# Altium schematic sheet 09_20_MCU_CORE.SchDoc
size 289 x 404 mm
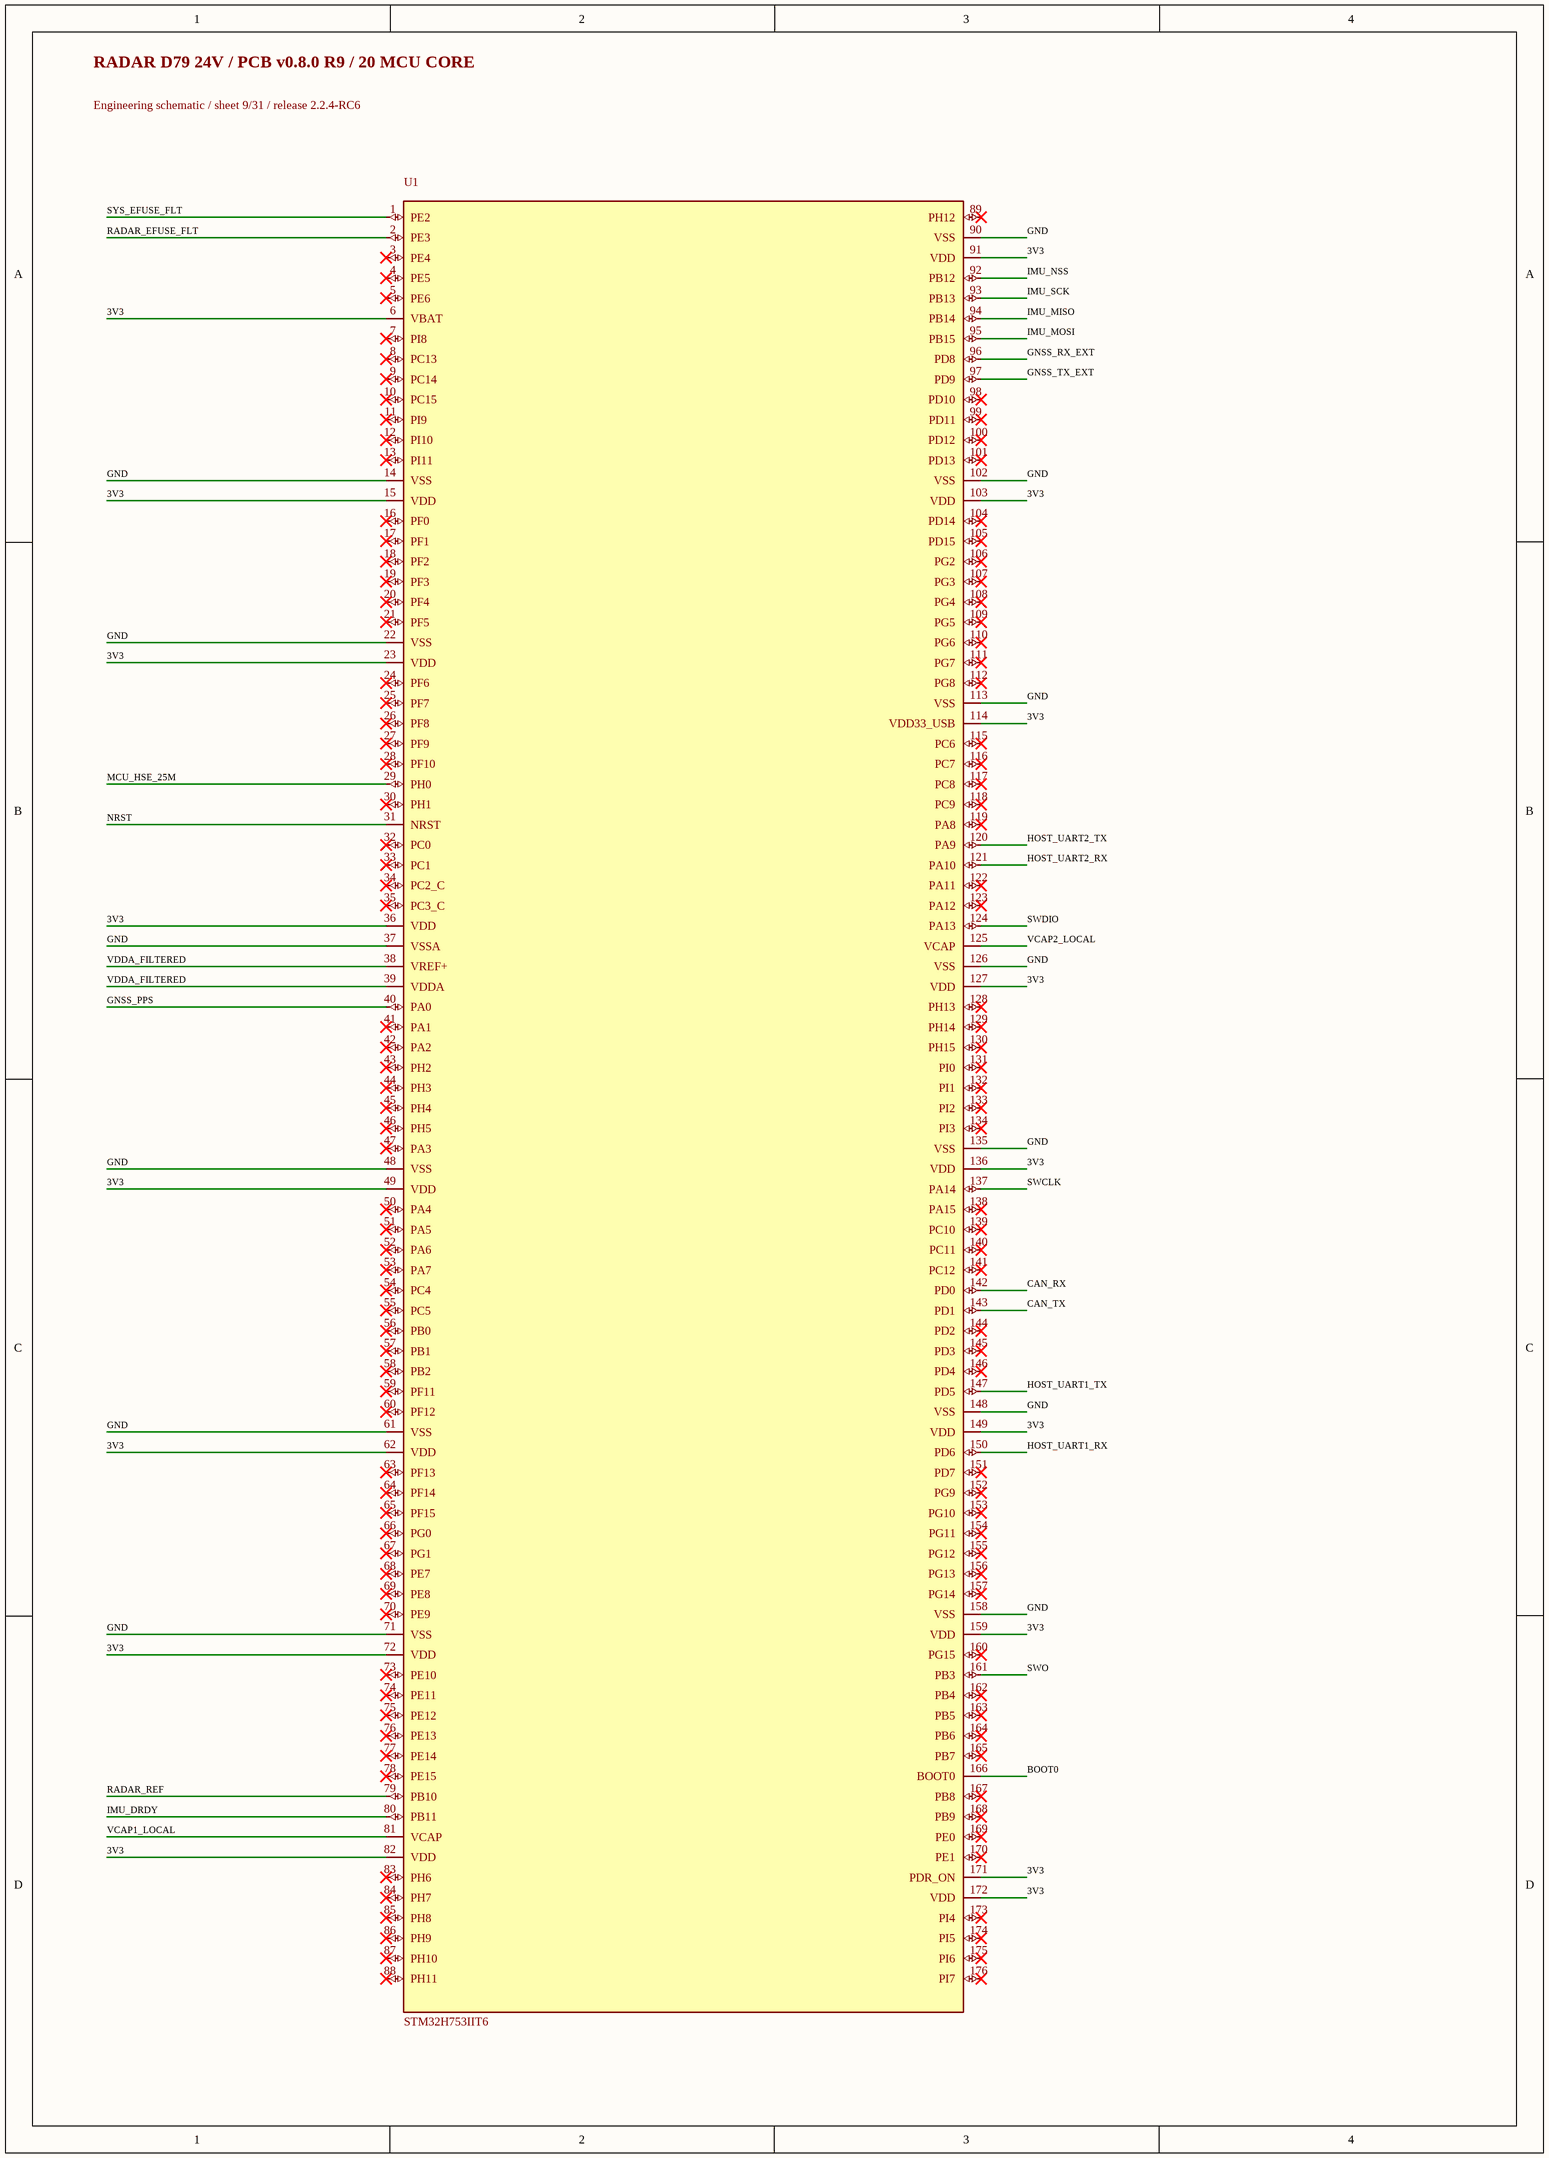
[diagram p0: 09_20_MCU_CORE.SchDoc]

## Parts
U1  STM32H753IIT6  [LQFP-176_24x24mm_P0.5mm]

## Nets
3V3: U1.6(VBAT) U1.15(VDD) U1.23(VDD) U1.36(VDD) U1.49(VDD) U1.62(VDD) U1.72(VDD) U1.82(VDD) U1.91(VDD) U1.103(VDD) U1.114(VDD33_USB) U1.127(VDD) U1.136(VDD) U1.149(VDD) U1.159(VDD) U1.171(PDR_ON) U1.172(VDD)
BOOT0: U1.166(BOOT0)
CAN_RX: U1.142(PD0)
CAN_TX: U1.143(PD1)
GND: U1.14(VSS) U1.22(VSS) U1.37(VSSA) U1.48(VSS) U1.61(VSS) U1.71(VSS) U1.90(VSS) U1.102(VSS) U1.113(VSS) U1.126(VSS) U1.135(VSS) U1.148(VSS) U1.158(VSS)
GNSS_PPS: U1.40(PA0)
GNSS_RX_EXT: U1.96(PD8)
GNSS_TX_EXT: U1.97(PD9)
HOST_UART1_RX: U1.150(PD6)
HOST_UART1_TX: U1.147(PD5)
HOST_UART2_RX: U1.121(PA10)
HOST_UART2_TX: U1.120(PA9)
IMU_DRDY: U1.80(PB11)
IMU_MISO: U1.94(PB14)
IMU_MOSI: U1.95(PB15)
IMU_NSS: U1.92(PB12)
IMU_SCK: U1.93(PB13)
MCU_HSE_25M: U1.29(PH0)
NRST: U1.31(NRST)
RADAR_EFUSE_FLT: U1.2(PE3)
RADAR_REF: U1.79(PB10)
SWCLK: U1.137(PA14)
SWDIO: U1.124(PA13)
SWO: U1.161(PB3)
SYS_EFUSE_FLT: U1.1(PE2)
VCAP1_LOCAL: U1.81(VCAP)
VCAP2_LOCAL: U1.125(VCAP)
VDDA_FILTERED: U1.38(VREF+) U1.39(VDDA)

Not connected (* = marked no-connect by the designer): U1 3(PE4)* 4(PE5)* 5(PE6)* 7(PI8)* 8(PC13)* 9(PC14)* 10(PC15)* 11(PI9)* 12(PI10)* 13(PI11)* 16(PF0)* 17(PF1)* 18(PF2)* 19(PF3)* 20(PF4)* 21(PF5)* 24(PF6)* 25(PF7)* 26(PF8)* 27(PF9)* 28(PF10)* 30(PH1)* 32(PC0)* 33(PC1)* 34(PC2_C)* 35(PC3_C)* 41(PA1)* 42(PA2)* 43(PH2)* 44(PH3)* 45(PH4)* 46(PH5)* 47(PA3)* 50(PA4)* 51(PA5)* 52(PA6)* 53(PA7)* 54(PC4)* 55(PC5)* 56(PB0)* 57(PB1)* 58(PB2)* 59(PF11)* 60(PF12)* 63(PF13)* 64(PF14)* 65(PF15)* 66(PG0)* 67(PG1)* 68(PE7)* 69(PE8)* 70(PE9)* 73(PE10)* 74(PE11)* 75(PE12)* 76(PE13)* 77(PE14)* 78(PE15)* 83(PH6)* 84(PH7)* 85(PH8)* 86(PH9)* 87(PH10)* 88(PH11)* 89(PH12)* 98(PD10)* 99(PD11)* 100(PD12)* 101(PD13)* 104(PD14)* 105(PD15)* 106(PG2)* 107(PG3)* 108(PG4)* 109(PG5)* 110(PG6)* 111(PG7)* 112(PG8)* 115(PC6)* 116(PC7)* 117(PC8)* 118(PC9)* 119(PA8)* 122(PA11)* 123(PA12)* 128(PH13)* 129(PH14)* 130(PH15)* 131(PI0)* 132(PI1)* 133(PI2)* 134(PI3)* 138(PA15)* 139(PC10)* 140(PC11)* 141(PC12)* 144(PD2)* 145(PD3)* 146(PD4)* 151(PD7)* 152(PG9)* 153(PG10)* 154(PG11)* 155(PG12)* 156(PG13)* 157(PG14)* 160(PG15)* 162(PB4)* 163(PB5)* 164(PB6)* 165(PB7)* 167(PB8)* 168(PB9)* 169(PE0)* 170(PE1)* 173(PI4)* 174(PI5)* 175(PI6)* 176(PI7)*

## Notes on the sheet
- RADAR D79 24V / PCB v0.8.0 R9 / 20 MCU CORE
- Engineering schematic / sheet 9/31 / release 2.2.4-RC6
